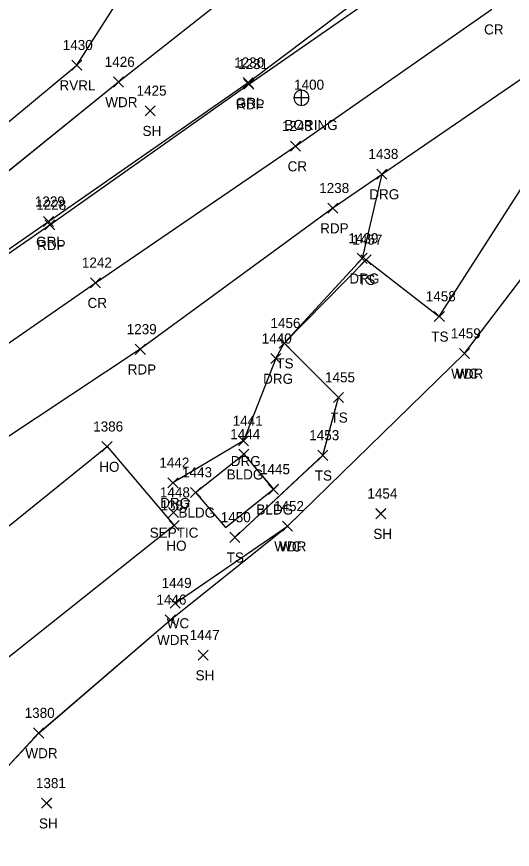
# Model space of a CAD drawing. Extents: x 1528286 to 1556263, y 492387 to 508952.
# Drawn here: x 1529016.8 to 1529115, y 492934.8 to 493100 of the extents above; entities that cross this region are included whole.
import ezdxf

# ---------------------------------------------------------------- set-up
doc = ezdxf.new("R2010")
doc.units = 0
for name, color, linetype in [('G_A', 7, 'Continuous'), ('G_I', 7, 'Continuous'), ('GA_P', 7, 'Continuous'), ('L_A', 7, 'Continuous'), ('L_I', 7, 'Continuous'), ('L_TIC', 7, 'Continuous'), ('LAWA', 7, 'Continuous'), ('LAWE', 7, 'Continuous'), ('LBC', 7, 'Continuous'), ('LELB', 7, 'Continuous'), ('P_A', 7, 'Continuous'), ('P_I', 7, 'Continuous'), ('P_TIC', 7, 'Continuous'), ('PET', 7, 'Continuous'), ('PRC', 7, 'Continuous'), ('R_A', 7, 'Continuous'), ('R_I', 7, 'Continuous'), ('R_TIC', 7, 'Continuous'), ('RDG', 7, 'Continuous'), ('RGR', 7, 'Continuous'), ('U_A', 7, 'Continuous'), ('U_I', 7, 'Continuous'), ('U_TIC', 7, 'Continuous')]:
    doc.layers.add(name, color=color, linetype=linetype)

msp = doc.modelspace()

# ---------------------------------------------------------------- linework, layer by layer
at = {"layer": 'GA_P'}
for p, q in [((1529073.21, 493083.9), (1529073.21, 493085.4)), ((1529073.21, 493083.9), (1529073.21, 493085.4)), ((1529073.21, 493083.9), (1529071.71, 493083.9)), ((1529073.21, 493083.9), (1529071.71, 493083.9)), ((1529074.71, 493083.9), (1529073.21, 493083.9)), ((1529073.21, 493082.4), (1529073.21, 493083.9)), ((1529074.71, 493083.9), (1529073.21, 493083.9)), ((1529073.21, 493082.4), (1529073.21, 493083.9))]:
    msp.add_line(p, q, dxfattribs=at)
for start, end in [(90, 180), (90, 180), (0, 90), (0, 90), (180, 270), (180, 270), (270, 0), (270, 0)]:
    msp.add_arc((1529073.21, 493083.9), 1.5, start, end, dxfattribs=at)
at = {"layer": 'L_TIC'}
for points in [[(1529027.67, 493089.37), (1529029.67, 493091.37)], [(1529029.67, 493089.37), (1529027.67, 493091.37)], [(1529027.67, 493089.37), (1529029.67, 493091.37)], [(1529029.67, 493089.37), (1529027.67, 493091.37)], [(1529035.96, 493086.03), (1529037.96, 493088.03)], [(1529037.96, 493086.03), (1529035.96, 493088.03)], [(1529035.96, 493086.03), (1529037.96, 493088.03)], [(1529037.96, 493086.03), (1529035.96, 493088.03)], [(1529042.22, 493080.32), (1529044.22, 493082.32)], [(1529044.22, 493080.32), (1529042.22, 493082.32)], [(1529042.22, 493080.32), (1529044.22, 493082.32)], [(1529044.22, 493080.32), (1529042.22, 493082.32)], [(1529085.02, 493050.77), (1529087.02, 493052.77)], [(1529087.02, 493050.77), (1529085.02, 493052.77)], [(1529085.02, 493050.77), (1529087.02, 493052.77)], [(1529087.02, 493050.77), (1529085.02, 493052.77)], [(1529099.55, 493039.52), (1529101.55, 493041.52)], [(1529101.55, 493039.52), (1529099.55, 493041.52)], [(1529099.55, 493039.52), (1529101.55, 493041.52)], [(1529101.55, 493039.52), (1529099.55, 493041.52)], [(1529068.82, 493034.21), (1529070.82, 493036.21)], [(1529070.82, 493034.21), (1529068.82, 493036.21)], [(1529068.82, 493034.21), (1529070.82, 493036.21)], [(1529070.82, 493034.21), (1529068.82, 493036.21)], [(1529104.52, 493032.17), (1529106.52, 493034.17)], [(1529106.52, 493032.17), (1529104.52, 493034.17)], [(1529104.52, 493032.17), (1529106.52, 493034.17)], [(1529106.52, 493032.17), (1529104.52, 493034.17)], [(1529104.52, 493032.17), (1529106.52, 493034.17)], [(1529106.52, 493032.17), (1529104.52, 493034.17)], [(1529104.52, 493032.17), (1529106.52, 493034.17)], [(1529106.52, 493032.17), (1529104.52, 493034.17)], [(1529079.57, 493023.46), (1529081.57, 493025.46)], [(1529081.57, 493023.46), (1529079.57, 493025.46)], [(1529079.57, 493023.46), (1529081.57, 493025.46)], [(1529081.57, 493023.46), (1529079.57, 493025.46)], [(1529033.67, 493013.69), (1529035.67, 493015.69)], [(1529035.67, 493013.69), (1529033.67, 493015.69)], [(1529033.67, 493013.69), (1529035.67, 493015.69)], [(1529035.67, 493013.69), (1529033.67, 493015.69)], [(1529060.79, 493012.17), (1529062.79, 493014.17)], [(1529062.79, 493012.17), (1529060.79, 493014.17)], [(1529060.79, 493012.17), (1529062.79, 493014.17)], [(1529062.79, 493012.17), (1529060.79, 493014.17)], [(1529076.45, 493011.96), (1529078.45, 493013.96)], [(1529078.45, 493011.96), (1529076.45, 493013.96)], [(1529076.46, 493011.97), (1529078.46, 493013.97)], [(1529078.46, 493011.97), (1529076.46, 493013.97)], [(1529066.68, 493005.21), (1529068.68, 493007.21)], [(1529068.68, 493005.21), (1529066.68, 493007.21)], [(1529066.69, 493005.22), (1529068.69, 493007.22)], [(1529068.69, 493005.22), (1529066.69, 493007.22)], [(1529051.24, 493004.61), (1529053.24, 493006.61)], [(1529053.24, 493004.61), (1529051.24, 493006.61)], [(1529051.24, 493004.61), (1529053.24, 493006.61)], [(1529053.24, 493004.61), (1529051.24, 493006.61)], [(1529087.97, 493000.39), (1529089.97, 493002.39)], [(1529089.97, 493000.39), (1529087.97, 493002.39)], [(1529087.97, 493000.38), (1529089.97, 493002.38)], [(1529089.97, 493000.38), (1529087.97, 493002.38)], [(1529046.99, 492998.03), (1529048.99, 493000.03)], [(1529048.99, 492998.03), (1529046.99, 493000.03)], [(1529046.99, 492998.03), (1529048.99, 493000.03)], [(1529048.99, 492998.03), (1529046.99, 493000.03)], [(1529069.46, 492997.89), (1529071.46, 492999.89)], [(1529071.46, 492997.89), (1529069.46, 492999.89)], [(1529069.46, 492997.89), (1529071.46, 492999.89)], [(1529071.46, 492997.89), (1529069.46, 492999.89)], [(1529069.46, 492997.89), (1529071.46, 492999.89)], [(1529071.46, 492997.89), (1529069.46, 492999.89)], [(1529069.46, 492997.89), (1529071.46, 492999.89)], [(1529071.46, 492997.89), (1529069.46, 492999.89)], [(1529058.99, 492995.69), (1529060.99, 492997.69)], [(1529060.99, 492995.69), (1529058.99, 492997.69)], [(1529058.99, 492995.69), (1529060.99, 492997.69)], [(1529060.99, 492995.69), (1529058.99, 492997.69)], [(1529047.19, 492982.65), (1529049.19, 492984.65)], [(1529049.19, 492982.65), (1529047.19, 492984.65)], [(1529047.19, 492982.65), (1529049.19, 492984.65)], [(1529049.19, 492982.65), (1529047.19, 492984.65)], [(1529046.22, 492979.34), (1529048.22, 492981.34)], [(1529048.22, 492979.34), (1529046.22, 492981.34)], [(1529046.22, 492979.34), (1529048.22, 492981.34)], [(1529048.22, 492979.34), (1529046.22, 492981.34)], [(1529052.74, 492972.32), (1529054.74, 492974.32)], [(1529054.74, 492972.32), (1529052.74, 492974.32)], [(1529052.74, 492972.32), (1529054.74, 492974.32)], [(1529054.74, 492972.32), (1529052.74, 492974.32)], [(1529020.11, 492956.87), (1529022.11, 492958.87)], [(1529022.11, 492956.87), (1529020.11, 492958.87)], [(1529020.12, 492956.87), (1529022.12, 492958.87)], [(1529022.12, 492956.87), (1529020.12, 492958.87)], [(1529021.69, 492942.94), (1529023.69, 492944.94)], [(1529023.69, 492942.94), (1529021.69, 492944.94)], [(1529021.7, 492942.94), (1529023.7, 492944.94)], [(1529023.7, 492942.94), (1529021.7, 492944.94)]]:
    msp.add_lwpolyline(points, dxfattribs=at)
at = {"layer": 'LAWA'}
for points in [[(1529161.79, 493169.98), (1529145.79, 493161.64), (1529103.54, 493137.09), (1529078.89, 493120.12), (1529036.96, 493087.03), (1528996.19, 493054.04), (1528954.46, 493025.37)], [(1529161.79, 493169.98), (1529145.79, 493161.64), (1529103.54, 493137.09), (1529078.89, 493120.12), (1529036.96, 493087.03), (1528996.19, 493054.03), (1528954.46, 493025.38)], [(1529047.22, 492980.34), (1529070.46, 492998.89), (1529105.52, 493033.17), (1529129.51, 493064.68), (1529152.67, 493077.07), (1529193.68, 493070.17)], [(1529047.22, 492980.34), (1529070.46, 492998.89), (1529105.52, 493033.17), (1529129.5, 493064.68), (1529152.67, 493077.07), (1529193.68, 493070.17)], [(1529021.11, 492957.87), (1529047.22, 492980.34)], [(1529021.12, 492957.87), (1529047.22, 492980.34)], [(1528991.4, 492934.8), (1529011.39, 492947.38), (1529021.11, 492957.87)], [(1528991.4, 492934.79), (1529011.39, 492947.38), (1529021.12, 492957.87)]]:
    msp.add_lwpolyline(points, dxfattribs=at)
at = {"layer": 'LAWE'}
for points in [[(1528993.43, 493061.12), (1529028.67, 493090.37), (1529051.82, 493126.54), (1529095.12, 493164.29)], [(1528993.43, 493061.13), (1529028.67, 493090.37), (1529051.83, 493126.54), (1529095.12, 493164.29)], [(1529048.19, 492983.65), (1529070.46, 492998.89), (1529105.52, 493033.17), (1529129.51, 493064.68), (1529144.61, 493080.72), (1529192.94, 493079.96)], [(1529048.19, 492983.65), (1529070.46, 492998.89), (1529105.52, 493033.17), (1529129.5, 493064.68), (1529144.6, 493080.72), (1529192.94, 493079.96)]]:
    msp.add_lwpolyline(points, dxfattribs=at)
at = {"layer": 'LBC'}
for p, q in [((1529052.24, 493005.61), (1529058.14, 492998.65)), ((1529058.14, 492998.65), (1529067.69, 493006.22))]:
    msp.add_line(p, q, dxfattribs=at)
for points in [[(1529001.83, 492962.36), (1528989.17, 492977.94), (1529034.67, 493014.69), (1529047.99, 492999.03), (1529001.83, 492962.36)], [(1529001.83, 492962.36), (1528989.17, 492977.94), (1529034.67, 493014.69), (1529047.99, 492999.03), (1529001.83, 492962.36)], [(1529052.24, 493005.61), (1529061.79, 493013.17), (1529067.69, 493006.22)], [(1529052.24, 493005.61), (1529061.79, 493013.17), (1529067.68, 493006.21)]]:
    msp.add_lwpolyline(points, dxfattribs=at)
at = {"layer": 'LELB'}
for points in [[(1529059.99, 492996.69), (1529077.46, 493012.97), (1529080.57, 493024.46), (1529069.82, 493035.21), (1529086.02, 493051.77), (1529100.55, 493040.52), (1529121.47, 493073.2), (1529138.52, 493085.85), (1529153.74, 493098.53), (1529177.1, 493090.51), (1529200.14, 493087.51)], [(1529059.99, 492996.69), (1529077.45, 493012.96), (1529080.57, 493024.46), (1529069.82, 493035.21), (1529086.02, 493051.77), (1529100.55, 493040.52), (1529121.47, 493073.2), (1529138.52, 493085.85), (1529153.74, 493098.53), (1529177.1, 493090.51), (1529200.14, 493087.51)]]:
    msp.add_lwpolyline(points, dxfattribs=at)
at = {"layer": 'P_TIC'}
for points in [[(1529061.76, 493085.59), (1529063.76, 493087.59)], [(1529063.76, 493085.59), (1529061.76, 493087.59)], [(1529061.76, 493085.59), (1529063.76, 493087.59)], [(1529063.76, 493085.59), (1529061.76, 493087.59)], [(1529071.04, 493073.3), (1529073.04, 493075.3)], [(1529073.04, 493073.3), (1529071.04, 493075.3)], [(1529071.04, 493073.3), (1529073.04, 493075.3)], [(1529073.04, 493073.3), (1529071.04, 493075.3)], [(1529078.43, 493061), (1529080.43, 493063)], [(1529080.43, 493061), (1529078.43, 493063)], [(1529078.43, 493061), (1529080.43, 493063)], [(1529080.43, 493061), (1529078.43, 493063)], [(1529022.32, 493057.68), (1529024.32, 493059.68)], [(1529024.32, 493057.68), (1529022.32, 493059.68)], [(1529022.32, 493057.68), (1529024.32, 493059.68)], [(1529024.32, 493057.68), (1529022.32, 493059.68)], [(1529031.37, 493046.2), (1529033.37, 493048.2)], [(1529033.37, 493046.2), (1529031.37, 493048.2)], [(1529031.37, 493046.2), (1529033.37, 493048.2)], [(1529033.37, 493046.2), (1529031.37, 493048.2)], [(1529040.27, 493033), (1529042.27, 493035)], [(1529042.27, 493033), (1529040.27, 493035)], [(1529040.27, 493033), (1529042.27, 493035)], [(1529042.27, 493033), (1529040.27, 493035)]]:
    msp.add_lwpolyline(points, dxfattribs=at)
at = {"layer": 'PET'}
msp.add_lwpolyline([(1528981.67, 493029.84), (1529023.32, 493058.68), (1529062.76, 493086.59), (1529101.46, 493113.53), (1529137.06, 493138.01), (1529145.3, 493125.26), (1529153.7, 493113.65), (1529119.46, 493089.42), (1529079.43, 493062), (1529041.27, 493034), (1528999.91, 493006.62)], dxfattribs=at)
msp.add_lwpolyline([(1528981.67, 493029.84), (1529023.32, 493058.68), (1529062.76, 493086.59), (1529101.46, 493113.53), (1529137.06, 493138.01), (1529145.3, 493125.26), (1529153.7, 493113.65), (1529119.46, 493089.42), (1529079.43, 493062), (1529041.27, 493034), (1528999.91, 493006.62)], dxfattribs=at)
at = {"layer": 'PRC'}
msp.add_lwpolyline([(1528990.43, 493018.09), (1529032.37, 493047.2), (1529072.04, 493074.3), (1529110.99, 493101.46)], dxfattribs=at)
msp.add_lwpolyline([(1528990.43, 493018.09), (1529032.37, 493047.2), (1529072.04, 493074.3), (1529110.99, 493101.46)], dxfattribs=at)
at = {"layer": 'R_TIC'}
for points in [[(1529061.66, 493085.9), (1529063.66, 493087.9)], [(1529063.66, 493085.9), (1529061.66, 493087.9)], [(1529061.66, 493085.9), (1529063.66, 493087.9)], [(1529063.66, 493085.9), (1529061.66, 493087.9)], [(1529088.17, 493067.76), (1529090.17, 493069.76)], [(1529090.17, 493067.76), (1529088.17, 493069.76)], [(1529088.17, 493067.76), (1529090.17, 493069.76)], [(1529090.17, 493067.76), (1529088.17, 493069.76)], [(1529022.06, 493058.33), (1529024.06, 493060.33)], [(1529024.06, 493058.33), (1529022.06, 493060.33)], [(1529022.06, 493058.33), (1529024.06, 493060.33)], [(1529024.06, 493058.33), (1529022.06, 493060.33)], [(1529084.23, 493051.04), (1529086.23, 493053.04)], [(1529086.23, 493051.04), (1529084.23, 493053.04)], [(1529084.23, 493051.04), (1529086.23, 493053.04)], [(1529086.23, 493051.04), (1529084.23, 493053.04)], [(1529067.12, 493031.15), (1529069.12, 493033.15)], [(1529069.12, 493031.15), (1529067.12, 493033.15)], [(1529067.12, 493031.15), (1529069.12, 493033.15)], [(1529069.12, 493031.15), (1529067.12, 493033.15)], [(1529060.71, 493014.82), (1529062.71, 493016.82)], [(1529062.71, 493014.82), (1529060.71, 493016.82)], [(1529060.71, 493014.82), (1529062.71, 493016.82)], [(1529062.71, 493014.82), (1529060.71, 493016.82)], [(1529046.74, 493006.52), (1529048.74, 493008.52)], [(1529048.74, 493006.52), (1529046.74, 493008.52)], [(1529046.74, 493006.52), (1529048.74, 493008.52)], [(1529048.74, 493006.52), (1529046.74, 493008.52)]]:
    msp.add_lwpolyline(points, dxfattribs=at)
at = {"layer": 'RDG'}
for points in [[(1529089.17, 493068.76), (1529085.23, 493052.04)], [(1529089.17, 493068.76), (1529085.23, 493052.04)], [(1529085.23, 493052.04), (1529069.82, 493035.21)], [(1529085.23, 493052.04), (1529069.82, 493035.21)], [(1529068.12, 493032.15), (1529069.82, 493035.21)], [(1529068.12, 493032.15), (1529069.82, 493035.21)], [(1529068.12, 493032.15), (1529061.71, 493015.82), (1529047.74, 493007.52)], [(1529068.12, 493032.15), (1529061.71, 493015.82), (1529047.74, 493007.52)]]:
    msp.add_lwpolyline(points, dxfattribs=at)
at = {"layer": 'RGR'}
msp.add_lwpolyline([(1528981.52, 493030.48), (1529023.06, 493059.33), (1529062.66, 493086.9), (1529100.29, 493115.36)], dxfattribs=at)
msp.add_lwpolyline([(1528981.52, 493030.48), (1529023.06, 493059.33), (1529062.66, 493086.9), (1529100.29, 493115.36)], dxfattribs=at)
at = {"layer": 'U_TIC'}
for points in [[(1529046.85, 493000.62), (1529048.85, 493002.62)], [(1529048.85, 493000.62), (1529046.85, 493002.62)], [(1529046.85, 493000.62), (1529048.85, 493002.62)], [(1529048.85, 493000.62), (1529046.85, 493002.62)]]:
    msp.add_lwpolyline(points, dxfattribs=at)

# ---------------------------------------------------------------- texts
at = {"layer": 'G_A'}
msp.add_text('BORING', height=2, dxfattribs=at).set_placement((1529069.84, 493077.5))
msp.add_text('BORING', height=2, dxfattribs=at).set_placement((1529069.84, 493077.5))
at = {"layer": 'G_I'}
msp.add_text('1400', height=2, dxfattribs=at).set_placement((1529071.75, 493085.5))
msp.add_text('1400', height=2, dxfattribs=at).set_placement((1529071.75, 493085.5))
at = {"layer": 'L_A'}
for s, p in [('RVRL', (1529025.24, 493085.37)), ('RVRL', (1529025.24, 493085.37)), ('WDR', (1529034.32, 493082.03)), ('WDR', (1529034.32, 493082.03)), ('SH', (1529041.71, 493076.32)), ('SH', (1529041.71, 493076.32)), ('TS', (1529084.43, 493046.77)), ('TS', (1529084.43, 493046.77)), ('TS', (1529098.96, 493035.52)), ('TS', (1529098.96, 493035.52)), ('TS', (1529068.23, 493030.21)), ('TS', (1529068.23, 493030.21)), ('WDR', (1529102.88, 493028.17)), ('WDR', (1529102.88, 493028.17)), ('WC', (1529103.82, 493028.17)), ('WC', (1529103.83, 493028.17)), ('TS', (1529078.98, 493019.46)), ('TS', (1529078.98, 493019.46)), ('HO', (1529033.12, 493009.69)), ('HO', (1529033.12, 493009.69)), ('BLDG', (1529058.38, 493008.17)), ('BLDG', (1529058.38, 493008.17)), ('TS', (1529075.86, 493007.97)), ('TS', (1529075.86, 493007.96)), ('BLDG', (1529048.83, 493000.61)), ('BLDG', (1529048.83, 493000.61)), ('BLDG', (1529064.28, 493001.21)), ('BLDG', (1529064.28, 493001.22)), ('SH', (1529087.46, 492996.39)), ('SH', (1529087.46, 492996.38)), ('HO', (1529046.43, 492994.03)), ('HO', (1529046.43, 492994.03)), ('WDR', (1529067.82, 492993.89)), ('WDR', (1529067.82, 492993.89)), ('WC', (1529068.77, 492993.89)), ('WC', (1529068.77, 492993.89)), ('TS', (1529058.4, 492991.69)), ('TS', (1529058.4, 492991.69)), ('WC', (1529046.5, 492978.65)), ('WC', (1529046.5, 492978.65)), ('WDR', (1529044.58, 492975.34)), ('WDR', (1529044.58, 492975.34)), ('SH', (1529052.22, 492968.32)), ('SH', (1529052.23, 492968.32)), ('WDR', (1529018.48, 492952.87)), ('WDR', (1529018.48, 492952.87)), ('SH', (1529021.18, 492938.94)), ('SH', (1529021.18, 492938.94))]:
    msp.add_text(s, height=2, dxfattribs=at).set_placement(p)
at = {"layer": 'L_I'}
for s, p in [('1430', (1529025.89, 493093.37)), ('1430', (1529025.89, 493093.37)), ('1426', (1529034.21, 493090.03)), ('1426', (1529034.21, 493090.03)), ('1425', (1529040.52, 493084.32)), ('1425', (1529040.52, 493084.32)), ('1457', (1529083.32, 493054.77)), ('1457', (1529083.32, 493054.77)), ('1458', (1529097.86, 493043.52)), ('1458', (1529097.86, 493043.52)), ('1456', (1529067.07, 493038.21)), ('1456', (1529067.07, 493038.21)), ('1459', (1529102.82, 493036.17)), ('1459', (1529102.82, 493036.17)), ('1459', (1529102.82, 493036.17)), ('1459', (1529102.82, 493036.17)), ('1455', (1529077.88, 493027.46)), ('1455', (1529077.88, 493027.46)), ('1386', (1529031.92, 493017.69)), ('1386', (1529031.92, 493017.69)), ('1444', (1529059.09, 493016.17)), ('1444', (1529059.09, 493016.17)), ('1453', (1529074.76, 493015.96)), ('1453', (1529074.76, 493015.97)), ('1443', (1529049.54, 493008.61)), ('1443', (1529049.54, 493008.61)), ('1445', (1529065, 493009.22)), ('1445', (1529064.99, 493009.21)), ('1454', (1529086.28, 493004.39)), ('1454', (1529086.28, 493004.38)), ('1387', (1529045.29, 493002.03)), ('1387', (1529045.29, 493002.03)), ('1452', (1529067.77, 493001.89)), ('1452', (1529067.77, 493001.89)), ('1452', (1529067.77, 493001.89)), ('1452', (1529067.77, 493001.89)), ('1450', (1529057.21, 492999.69)), ('1450', (1529057.21, 492999.69)), ('1449', (1529045.49, 492986.65)), ('1449', (1529045.49, 492986.65)), ('1446', (1529044.47, 492983.34)), ('1446', (1529044.47, 492983.34)), ('1447', (1529051.05, 492976.32)), ('1447', (1529051.04, 492976.32)), ('1380', (1529018.34, 492960.87)), ('1380', (1529018.34, 492960.87)), ('1381', (1529020.57, 492946.94)), ('1381', (1529020.57, 492946.94))]:
    msp.add_text(s, height=2, dxfattribs=at).set_placement(p)
at = {"layer": 'P_A'}
for s, p in [('CR', (1529109.42, 493096.46)), ('CR', (1529109.42, 493096.46)), ('RDP', (1529060.25, 493081.59)), ('RDP', (1529060.25, 493081.59)), ('CR', (1529070.47, 493069.3)), ('CR', (1529070.47, 493069.3)), ('RDP', (1529076.92, 493057)), ('RDP', (1529076.92, 493057)), ('RDP', (1529020.81, 493053.68)), ('RDP', (1529020.81, 493053.68)), ('CR', (1529030.8, 493042.2)), ('CR', (1529030.8, 493042.2)), ('RDP', (1529038.76, 493029)), ('RDP', (1529038.76, 493029))]:
    msp.add_text(s, height=2, dxfattribs=at).set_placement(p)
at = {"layer": 'P_I'}
for s, p in [('1231', (1529060.64, 493089.59)), ('1231', (1529060.64, 493089.59)), ('1243', (1529069.34, 493077.3)), ('1243', (1529069.34, 493077.3)), ('1238', (1529076.73, 493065)), ('1238', (1529076.73, 493065)), ('1228', (1529020.63, 493061.68)), ('1228', (1529020.63, 493061.68)), ('1242', (1529029.68, 493050.2)), ('1242', (1529029.68, 493050.2)), ('1239', (1529038.57, 493037)), ('1239', (1529038.57, 493037))]:
    msp.add_text(s, height=2, dxfattribs=at).set_placement(p)
at = {"layer": 'R_A'}
for s, p in [('GRL', (1529060.2, 493081.9)), ('GRL', (1529060.2, 493081.9)), ('DRG', (1529086.66, 493063.76)), ('DRG', (1529086.66, 493063.76)), ('GRL', (1529020.6, 493054.33)), ('GRL', (1529020.6, 493054.33)), ('DRG', (1529082.72, 493047.04)), ('DRG', (1529082.72, 493047.04)), ('DRG', (1529065.61, 493027.15)), ('DRG', (1529065.61, 493027.15)), ('DRG', (1529059.2, 493010.82)), ('DRG', (1529059.2, 493010.82)), ('DRG', (1529045.22, 493002.52)), ('DRG', (1529045.22, 493002.52))]:
    msp.add_text(s, height=2, dxfattribs=at).set_placement(p)
at = {"layer": 'R_I'}
for s, p in [('1230', (1529059.88, 493089.9)), ('1230', (1529059.88, 493089.9)), ('1438', (1529086.48, 493071.76)), ('1438', (1529086.48, 493071.76)), ('1229', (1529020.36, 493062.33)), ('1229', (1529020.36, 493062.33)), ('1439', (1529082.53, 493055.04)), ('1439', (1529082.53, 493055.04)), ('1440', (1529065.34, 493035.15)), ('1440', (1529065.34, 493035.15)), ('1441', (1529059.58, 493018.82)), ('1441', (1529059.58, 493018.82)), ('1442', (1529045.04, 493010.52)), ('1442', (1529045.04, 493010.52))]:
    msp.add_text(s, height=2, dxfattribs=at).set_placement(p)
at = {"layer": 'U_A'}
msp.add_text('SEPTIC', height=2, dxfattribs=at).set_placement((1529043.13, 492996.62))
msp.add_text('SEPTIC', height=2, dxfattribs=at).set_placement((1529043.13, 492996.62))
at = {"layer": 'U_I'}
msp.add_text('1448', height=2, dxfattribs=at).set_placement((1529045.15, 493004.62))
msp.add_text('1448', height=2, dxfattribs=at).set_placement((1529045.15, 493004.62))

doc.saveas('drawing.dxf')
